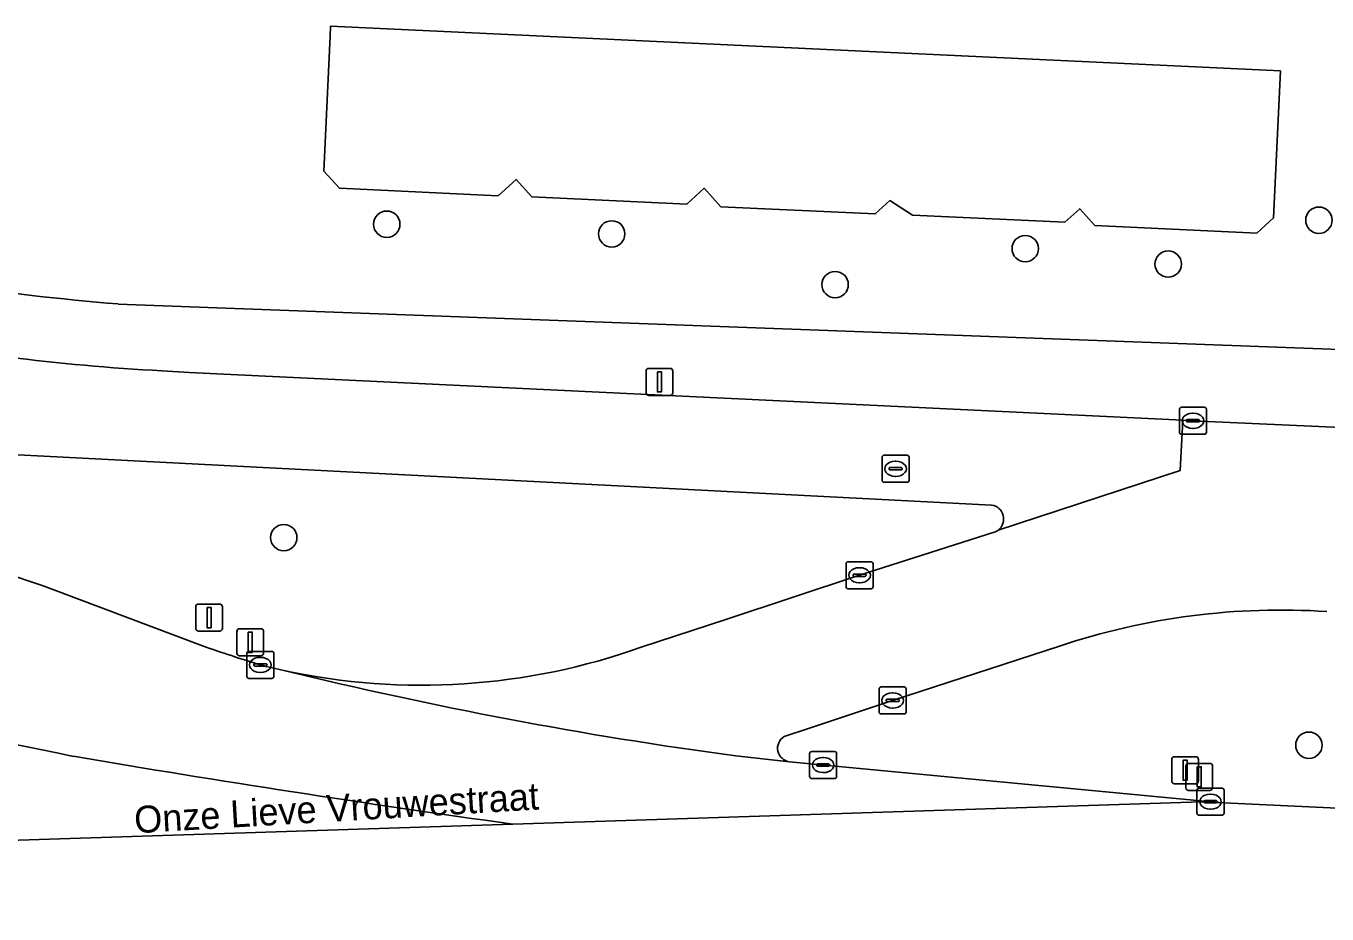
# Model space of a CAD drawing. Extents: x 161248 to 161848, y 384871 to 385383.
# Drawn here: x 161389.28 to 161437.48, y 384880.89 to 384913.79 of the extents above; entities that cross this region are included whole.
import ezdxf

# ---------------------------------------------------------------- set-up
doc = ezdxf.new("R2010")
doc.units = 0
for name, color, linetype in [('IMGEO_Berm_groen', 7, 'Continuous'), ('IMGEO_Boom', 7, 'Continuous'), ('IMGEO_Erf', 7, 'Continuous'), ('IMGEO_Fietspad_gesloten', 7, 'Continuous'), ('IMGEO_Kolk', 7, 'Continuous'), ('IMGEO_Lichtmast', 7, 'Continuous'), ('IMGEO_Openbare_ruimte_label', 7, 'Continuous'), ('IMGEO_Pand', 7, 'Continuous'), ('IMGEO_Rijbaan_lokaal_open', 7, 'Continuous'), ('IMGEO_Rijbaan_regionaal_gesloten', 7, 'Continuous'), ('IMGEO_Rioolput', 7, 'Continuous'), ('IMGEO_Verkeersbordpaal', 7, 'Continuous'), ('IMGEO_Voetpad_open', 7, 'Continuous')]:
    doc.layers.add(name, color=color, linetype=linetype)

msp = doc.modelspace()

# ---------------------------------------------------------------- linework, layer by layer
at = {"layer": 'IMGEO_Berm_groen'}
for points in [[(161425.059, 384896.042), (161385.143, 384898.097)], [(161412.072, 384890.772), (161415.208, 384891.797), (161420.164, 384893.441), (161425.158, 384895.035)], [(161390.211, 384892.939), (161395.816, 384890.82)], [(161427.57, 384890.811), (161421.391, 384888.8), (161418.346, 384887.783), (161417.374, 384887.467)], [(161417.572, 384886.526), (161433.198, 384885.047), (161433.661, 384885.003), (161462.543, 384883.65), (161521.484, 384880.889)], [(161336.645, 384880.9), (161352.375, 384882.439), (161407.315, 384884.216)]]:
    msp.add_lwpolyline(points, dxfattribs=at)
for centre, radius, start, end in [((161424.983, 384895.526), 0.521, 308.0291, 81.6103), ((161360.759, 384809.587), 88.402, 70.53961, 77.01299), ((161424.996, 384895.499), 0.492, 289.245, 308.7976), ((161435.777, 384866.344), 25.807, 86.2042, 108.542), ((161522.417, 385531.517), 658.036, 256.745177, 258.48305), ((161418.628, 384957.021), 70.021, 250.98646, 252.83384), ((161403.947, 384913.55), 24.183, 257.7953, 289.6306), ((161404.161, 384914.436), 25.095, 255.6989, 257.7469), ((161417.636, 384887.031), 0.509, 120.9475, 262.8176), ((161485.028, 385441.523), 562.698, 260.38423, 262.06157)]:
    msp.add_arc(centre, radius, start, end, dxfattribs=at)
at = {"layer": 'IMGEO_Boom'}
for centre in [(161402.645, 384906.447), (161437.186, 384906.596), (161410.979, 384906.088), (161426.304, 384905.543), (161431.601, 384904.972), (161419.258, 384904.209), (161398.828, 384894.835), (161436.816, 384887.142)]:
    msp.add_circle(centre, 0.489, dxfattribs=at)
at = {"layer": 'IMGEO_Erf'}
msp.add_lwpolyline([(161430.768, 384912.367), (161435.762, 384912.131), (161435.505, 384906.68), (161434.889, 384906.119), (161428.885, 384906.402), (161428.321, 384907.022), (161427.768, 384906.519), (161422.131, 384906.785), (161421.289, 384907.325), (161420.743, 384906.828), (161415.03, 384907.098), (161414.408, 384907.782), (161413.761, 384907.193), (161408.021, 384907.464), (161407.435, 384908.109), (161406.767, 384907.501), (161400.891, 384907.778), (161400.31, 384908.417), (161400.545, 384913.412), (161400.563, 384913.792)], close=True, dxfattribs=at)
msp.add_lwpolyline([(161392.69, 384903.491), (161446.603, 384901.485)], dxfattribs=at)
msp.add_arc((161401.795, 385012.165), 109.054, 258.46978, 265.21062, dxfattribs=at)
at = {"layer": 'IMGEO_Fietspad_gesloten'}
for points in [[(161432.148, 384899.181), (161395.318, 384900.953), (161394.326, 384901.014)], [(161425.304, 384895.116), (161432.042, 384897.321), (161432.148, 384899.181)], [(161385.143, 384898.097), (161425.059, 384896.042)]]:
    msp.add_lwpolyline(points, dxfattribs=at)
for centre, radius, start, end in [((161398.556, 384980.656), 79.754, 262.8094, 266.95981), ((161424.983, 384895.526), 0.521, 308.0291, 81.6103)]:
    msp.add_arc(centre, radius, start, end, dxfattribs=at)
at = {"layer": 'IMGEO_Kolk'}
for p, q in [((161432.018, 384898.738), (161432.018, 384899.59)), ((161432.093, 384899.664), (161432.945, 384899.664)), ((161432.506, 384899.444), (161432.531, 384899.444)), ((161433.019, 384899.59), (161433.019, 384898.738)), ((161432.277, 384899.158), (161432.277, 384899.17)), ((161432.715, 384899.121), (161432.317, 384899.121)), ((161432.32, 384899.207), (161432.718, 384899.207)), ((161432.761, 384899.17), (161432.761, 384899.158)), ((161432.945, 384898.664), (161432.093, 384898.664)), ((161432.529, 384898.884), (161432.504, 384898.884)), ((161419.663, 384893.015), (161419.663, 384893.867)), ((161419.738, 384893.941), (161420.59, 384893.941)), ((161420.151, 384893.721), (161420.176, 384893.721)), ((161420.664, 384893.867), (161420.664, 384893.015)), ((161419.922, 384893.435), (161419.922, 384893.447)), ((161420.36, 384893.398), (161419.962, 384893.398)), ((161419.965, 384893.484), (161420.363, 384893.484)), ((161420.174, 384893.161), (161420.149, 384893.161)), ((161420.406, 384893.447), (161420.406, 384893.435)), ((161420.59, 384892.941), (161419.738, 384892.941)), ((161397.461, 384889.693), (161397.461, 384890.545)), ((161397.536, 384890.619), (161398.388, 384890.619)), ((161397.949, 384890.399), (161397.974, 384890.399)), ((161398.462, 384890.545), (161398.462, 384889.693)), ((161397.72, 384890.113), (161397.72, 384890.125)), ((161398.158, 384890.076), (161397.76, 384890.076)), ((161397.763, 384890.162), (161398.161, 384890.162)), ((161397.972, 384889.839), (161397.947, 384889.839)), ((161398.204, 384890.125), (161398.204, 384890.113)), ((161398.388, 384889.619), (161397.536, 384889.619)), ((161420.965, 384889.3), (161421.817, 384889.3)), ((161420.89, 384888.374), (161420.89, 384889.226)), ((161421.149, 384888.794), (161421.149, 384888.806)), ((161421.192, 384888.843), (161421.59, 384888.843)), ((161421.378, 384889.08), (161421.403, 384889.08)), ((161421.633, 384888.806), (161421.633, 384888.794)), ((161421.891, 384889.226), (161421.891, 384888.374)), ((161421.587, 384888.757), (161421.189, 384888.757)), ((161421.401, 384888.52), (161421.376, 384888.52)), ((161421.817, 384888.3), (161420.965, 384888.3)), ((161418.39, 384886.908), (161419.242, 384886.908)), ((161418.315, 384885.982), (161418.315, 384886.834)), ((161418.574, 384886.402), (161418.574, 384886.414)), ((161418.617, 384886.451), (161419.015, 384886.451)), ((161418.803, 384886.688), (161418.828, 384886.688)), ((161419.058, 384886.414), (161419.058, 384886.402)), ((161419.316, 384886.834), (161419.316, 384885.982)), ((161419.242, 384885.908), (161418.39, 384885.908)), ((161419.012, 384886.365), (161418.614, 384886.365)), ((161418.826, 384886.128), (161418.801, 384886.128)), ((161432.668, 384884.624), (161432.668, 384885.476)), ((161432.743, 384885.55), (161433.595, 384885.55)), ((161433.669, 384885.476), (161433.669, 384884.624)), ((161432.927, 384885.044), (161432.927, 384885.056)), ((161433.365, 384885.007), (161432.967, 384885.007)), ((161432.97, 384885.093), (161433.368, 384885.093)), ((161433.156, 384885.33), (161433.181, 384885.33)), ((161433.411, 384885.056), (161433.411, 384885.044)), ((161433.595, 384884.55), (161432.743, 384884.55)), ((161433.179, 384884.77), (161433.154, 384884.77))]:
    msp.add_line(p, q, dxfattribs=at)
for points in [[(161432.018, 384898.738), (161432.018, 384899.59)], [(161432.093, 384899.664), (161432.945, 384899.664)], [(161433.019, 384899.59), (161433.019, 384898.738)], [(161432.945, 384898.664), (161432.093, 384898.664)], [(161419.663, 384893.015), (161419.663, 384893.867)], [(161419.738, 384893.941), (161420.59, 384893.941)], [(161420.664, 384893.867), (161420.664, 384893.015)], [(161420.59, 384892.941), (161419.738, 384892.941)], [(161397.461, 384889.693), (161397.461, 384890.545)], [(161397.536, 384890.619), (161398.388, 384890.619)], [(161398.462, 384890.545), (161398.462, 384889.693)], [(161398.388, 384889.619), (161397.536, 384889.619)], [(161420.965, 384889.3), (161421.817, 384889.3)], [(161420.89, 384888.374), (161420.89, 384889.226)], [(161421.891, 384889.226), (161421.891, 384888.374)], [(161421.817, 384888.3), (161420.965, 384888.3)], [(161418.39, 384886.908), (161419.242, 384886.908)], [(161418.315, 384885.982), (161418.315, 384886.834)], [(161419.316, 384886.834), (161419.316, 384885.982)], [(161419.242, 384885.908), (161418.39, 384885.908)], [(161432.668, 384884.624), (161432.668, 384885.476)], [(161432.743, 384885.55), (161433.595, 384885.55)], [(161433.669, 384885.476), (161433.669, 384884.624)], [(161433.595, 384884.55), (161432.743, 384884.55)]]:
    msp.add_lwpolyline(points, dxfattribs=at)
for centre, radius, start, end in [((161432.095, 384899.588), 0.0765, 91.552, 178.448), ((161432.095, 384899.588), 0.0765, 91.552, 178.448), ((161432.943, 384899.588), 0.0765, 1.552, 88.448), ((161432.943, 384899.588), 0.0765, 1.552, 88.448), ((161432.317, 384899.167), 0.0403, 85.8775, 175.7526), ((161432.314, 384899.157), 0.0366, 178.938, 274.7102), ((161432.718, 384899.164), 0.043, 264.8664, 352.4533), ((161432.722, 384899.169), 0.0386, 1.7309, 96.639), ((161432.095, 384898.74), 0.0765, 181.552, 268.448), ((161432.095, 384898.74), 0.0765, 181.552, 268.448), ((161432.943, 384898.74), 0.0765, 271.552, 358.448), ((161432.943, 384898.74), 0.0765, 271.552, 358.448), ((161419.74, 384893.865), 0.0765, 91.552, 178.448), ((161419.74, 384893.865), 0.0765, 91.552, 178.448), ((161420.588, 384893.865), 0.0765, 1.552, 88.448), ((161420.588, 384893.865), 0.0765, 1.552, 88.448), ((161419.962, 384893.444), 0.0403, 85.8775, 175.7526), ((161419.959, 384893.434), 0.0366, 178.938, 274.7102), ((161420.363, 384893.441), 0.043, 264.8664, 352.4533), ((161420.367, 384893.446), 0.0386, 1.7309, 96.639), ((161419.74, 384893.017), 0.0765, 181.552, 268.448), ((161419.74, 384893.017), 0.0765, 181.552, 268.448), ((161420.588, 384893.017), 0.0765, 271.552, 358.448), ((161420.588, 384893.017), 0.0765, 271.552, 358.448), ((161397.538, 384890.543), 0.0765, 91.552, 178.448), ((161397.538, 384890.543), 0.0765, 91.552, 178.448), ((161398.386, 384890.543), 0.0765, 1.552, 88.448), ((161398.386, 384890.543), 0.0765, 1.552, 88.448), ((161397.76, 384890.122), 0.0403, 85.8775, 175.7526), ((161397.757, 384890.112), 0.0366, 178.938, 274.7102), ((161398.161, 384890.119), 0.043, 264.8664, 352.4533), ((161398.165, 384890.124), 0.0386, 1.7309, 96.639), ((161397.538, 384889.695), 0.0765, 181.552, 268.448), ((161397.538, 384889.695), 0.0765, 181.552, 268.448), ((161398.386, 384889.695), 0.0765, 271.552, 358.448), ((161398.386, 384889.695), 0.0765, 271.552, 358.448), ((161420.967, 384889.224), 0.0765, 91.552, 178.448), ((161420.967, 384889.224), 0.0765, 91.552, 178.448), ((161421.815, 384889.224), 0.0765, 1.552, 88.448), ((161421.815, 384889.224), 0.0765, 1.552, 88.448), ((161421.189, 384888.803), 0.0403, 85.8775, 175.7526), ((161421.186, 384888.793), 0.0366, 178.938, 274.7102), ((161421.59, 384888.8), 0.043, 264.8664, 352.4533), ((161421.594, 384888.805), 0.0386, 1.7309, 96.639), ((161420.967, 384888.376), 0.0765, 181.552, 268.448), ((161420.967, 384888.376), 0.0765, 181.552, 268.448), ((161421.815, 384888.376), 0.0765, 271.552, 358.448), ((161421.815, 384888.376), 0.0765, 271.552, 358.448), ((161418.392, 384886.832), 0.0765, 91.552, 178.448), ((161418.392, 384886.832), 0.0765, 91.552, 178.448), ((161419.24, 384886.832), 0.0765, 1.552, 88.448), ((161419.24, 384886.832), 0.0765, 1.552, 88.448), ((161418.614, 384886.411), 0.0403, 85.8775, 175.7526), ((161418.611, 384886.401), 0.0366, 178.938, 274.7102), ((161419.015, 384886.408), 0.043, 264.8664, 352.4533), ((161419.019, 384886.413), 0.0386, 1.7309, 96.639), ((161418.392, 384885.984), 0.0765, 181.552, 268.448), ((161418.392, 384885.984), 0.0765, 181.552, 268.448), ((161419.24, 384885.984), 0.0765, 271.552, 358.448), ((161419.24, 384885.984), 0.0765, 271.552, 358.448), ((161432.745, 384885.474), 0.0765, 91.552, 178.448), ((161432.745, 384885.474), 0.0765, 91.552, 178.448), ((161433.593, 384885.474), 0.0765, 1.552, 88.448), ((161433.593, 384885.474), 0.0765, 1.552, 88.448), ((161432.967, 384885.053), 0.0403, 85.8775, 175.7526), ((161432.964, 384885.043), 0.0366, 178.938, 274.7102), ((161433.368, 384885.05), 0.043, 264.8664, 352.4533), ((161433.372, 384885.055), 0.0386, 1.7309, 96.639), ((161432.745, 384884.626), 0.0765, 181.552, 268.448), ((161432.745, 384884.626), 0.0765, 181.552, 268.448), ((161433.593, 384884.626), 0.0765, 271.552, 358.448), ((161433.593, 384884.626), 0.0765, 271.552, 358.448)]:
    msp.add_arc(centre, radius, start, end, dxfattribs=at)
for centre, major_axis, ratio, start_param, end_param in [((161432.505, 384899.164), (-0.387, 0.002), 0.722429, 4.712389, 7.853982), ((161432.53, 384899.164), (-0.39, 0.002), 0.717154, 1.570796, 4.712389), ((161420.15, 384893.441), (-0.387, 0.002), 0.722429, 4.712389, 7.853982), ((161420.175, 384893.441), (-0.39, 0.002), 0.717154, 1.570796, 4.712389), ((161397.948, 384890.119), (-0.387, 0.002), 0.722429, 4.712389, 7.853982), ((161397.973, 384890.119), (-0.39, 0.002), 0.717154, 1.570796, 4.712389), ((161421.377, 384888.8), (-0.387, 0.002), 0.722429, 4.712389, 7.853982), ((161421.402, 384888.8), (-0.39, 0.002), 0.717154, 1.570796, 4.712389), ((161418.802, 384886.408), (-0.387, 0.002), 0.722429, 4.712389, 7.853982), ((161418.827, 384886.408), (-0.39, 0.002), 0.717154, 1.570796, 4.712389), ((161433.155, 384885.05), (-0.387, 0.002), 0.722429, 4.712389, 7.853982), ((161433.18, 384885.05), (-0.39, 0.002), 0.717154, 1.570796, 4.712389)]:
    msp.add_ellipse(centre, major_axis=major_axis, ratio=ratio, start_param=start_param, end_param=end_param, dxfattribs=at)
at = {"layer": 'IMGEO_Lichtmast'}
for p, q in [((161412.255, 384900.206), (161412.255, 384901.006)), ((161412.255, 384901.006), (161412.255, 384900.206)), ((161412.355, 384901.106), (161413.145, 384901.106)), ((161413.145, 384901.106), (161412.355, 384901.106)), ((161413.245, 384901.006), (161413.245, 384900.206)), ((161413.245, 384900.206), (161413.245, 384901.006)), ((161413.145, 384900.106), (161412.355, 384900.106)), ((161412.355, 384900.106), (161413.145, 384900.106)), ((161395.565, 384891.472), (161395.565, 384892.272)), ((161395.565, 384892.272), (161395.565, 384891.472)), ((161395.665, 384892.372), (161396.455, 384892.372)), ((161396.455, 384892.372), (161395.665, 384892.372)), ((161396.555, 384892.272), (161396.555, 384891.472)), ((161396.555, 384891.472), (161396.555, 384892.272)), ((161396.455, 384891.372), (161395.665, 384891.372)), ((161395.665, 384891.372), (161396.455, 384891.372)), ((161431.734, 384885.817), (161431.734, 384886.617)), ((161431.734, 384886.617), (161431.734, 384885.817)), ((161431.834, 384886.717), (161432.624, 384886.717)), ((161432.624, 384886.717), (161431.834, 384886.717)), ((161432.724, 384886.617), (161432.724, 384885.817)), ((161432.724, 384885.817), (161432.724, 384886.617)), ((161432.624, 384885.717), (161431.834, 384885.717)), ((161431.834, 384885.717), (161432.624, 384885.717))]:
    msp.add_line(p, q, dxfattribs=at)
for points in [[(161412.675, 384900.981), (161412.825, 384900.981), (161412.825, 384900.231), (161412.675, 384900.231), (161412.675, 384900.981)], [(161395.985, 384892.247), (161396.135, 384892.247), (161396.135, 384891.497), (161395.985, 384891.497), (161395.985, 384892.247)], [(161432.154, 384886.592), (161432.304, 384886.592), (161432.304, 384885.842), (161432.154, 384885.842), (161432.154, 384886.592)]]:
    msp.add_lwpolyline(points, dxfattribs=at)
for centre, start, end in [((161412.355, 384901.006), 90, 180), ((161412.355, 384901.006), 90, 180), ((161413.145, 384901.006), 0, 90), ((161413.145, 384901.006), 360, 90), ((161412.355, 384900.206), 180, 270), ((161412.355, 384900.206), 180, 270), ((161413.145, 384900.206), 270, 0), ((161413.145, 384900.206), 270, 0), ((161395.665, 384892.272), 90, 180), ((161395.665, 384892.272), 90, 180), ((161396.455, 384892.272), 0, 90), ((161396.455, 384892.272), 360, 90), ((161395.665, 384891.472), 180, 270), ((161395.665, 384891.472), 180, 270), ((161396.455, 384891.472), 270, 0), ((161396.455, 384891.472), 270, 0), ((161431.834, 384886.617), 90, 180), ((161431.834, 384886.617), 90, 180), ((161432.624, 384886.617), 0, 90), ((161432.624, 384886.617), 360, 90), ((161431.834, 384885.817), 180, 270), ((161431.834, 384885.817), 180, 270), ((161432.624, 384885.817), 270, 0), ((161432.624, 384885.817), 270, 0)]:
    msp.add_arc(centre, 0.1, start, end, dxfattribs=at)
at = {"layer": 'IMGEO_Pand'}
msp.add_lwpolyline([(161400.31, 384908.417), (161400.891, 384907.778), (161406.767, 384907.501), (161407.435, 384908.109), (161408.021, 384907.464), (161413.761, 384907.193), (161414.408, 384907.782), (161415.03, 384907.098), (161420.743, 384906.828), (161421.289, 384907.325), (161422.131, 384906.785), (161427.768, 384906.519), (161428.321, 384907.022), (161428.885, 384906.402), (161434.889, 384906.119), (161435.505, 384906.68), (161435.762, 384912.131), (161430.768, 384912.367), (161400.563, 384913.792), (161400.545, 384913.412)], close=True, dxfattribs=at)
at = {"layer": 'IMGEO_Rijbaan_lokaal_open'}
for points in [[(161447.197, 384898.503), (161445.976, 384898.555), (161432.519, 384899.164), (161432.148, 384899.181), (161432.042, 384897.321), (161425.304, 384895.116)], [(161425.158, 384895.035), (161420.164, 384893.441), (161415.208, 384891.797), (161412.072, 384890.772)], [(161417.374, 384887.467), (161418.346, 384887.783), (161421.391, 384888.8), (161427.57, 384890.811)], [(161415.575, 384886.745), (161417.572, 384886.526)]]:
    msp.add_lwpolyline(points, dxfattribs=at)
for centre, radius, start, end in [((161424.996, 384895.499), 0.492, 289.245, 308.7976), ((161435.777, 384866.344), 25.807, 86.2042, 108.542), ((161403.947, 384913.55), 24.183, 257.7953, 289.6306), ((161437.172, 385046.676), 161.382, 256.2579, 262.30943), ((161417.636, 384887.031), 0.509, 120.9475, 262.8176)]:
    msp.add_arc(centre, radius, start, end, dxfattribs=at)
at = {"layer": 'IMGEO_Rijbaan_regionaal_gesloten'}
for points in [[(161395.816, 384890.82), (161390.211, 384892.939)], [(161433.661, 384885.003), (161433.198, 384885.047), (161417.572, 384886.526), (161415.575, 384886.745)], [(161407.315, 384884.216), (161432.831, 384885.042), (161433.661, 384885.003)]]:
    msp.add_lwpolyline(points, dxfattribs=at)
for centre, radius, start, end in [((161360.759, 384809.587), 88.402, 70.53961, 77.01299), ((161522.417, 385531.517), 658.036, 256.745177, 258.48305), ((161418.628, 384957.021), 70.021, 250.98646, 252.83384), ((161404.161, 384914.436), 25.095, 255.6989, 257.7469), ((161437.172, 385046.676), 161.382, 256.2579, 262.30943), ((161485.028, 385441.523), 562.698, 260.38423, 262.06157)]:
    msp.add_arc(centre, radius, start, end, dxfattribs=at)
at = {"layer": 'IMGEO_Rioolput'}
for p, q in [((161420.998, 384896.959), (161420.998, 384897.811)), ((161421.073, 384897.885), (161421.925, 384897.885)), ((161421.486, 384897.665), (161421.511, 384897.665)), ((161421.999, 384897.811), (161421.999, 384896.959)), ((161421.257, 384897.379), (161421.257, 384897.391)), ((161421.695, 384897.342), (161421.297, 384897.342)), ((161421.3, 384897.428), (161421.698, 384897.428)), ((161421.509, 384897.105), (161421.484, 384897.105)), ((161421.741, 384897.391), (161421.741, 384897.379)), ((161421.925, 384896.885), (161421.073, 384896.885))]:
    msp.add_line(p, q, dxfattribs=at)
for points in [[(161420.998, 384896.959), (161420.998, 384897.811)], [(161421.073, 384897.885), (161421.925, 384897.885)], [(161421.999, 384897.811), (161421.999, 384896.959)], [(161421.925, 384896.885), (161421.073, 384896.885)]]:
    msp.add_lwpolyline(points, dxfattribs=at)
for centre, radius, start, end in [((161421.075, 384897.809), 0.0765, 91.552, 178.448), ((161421.075, 384897.809), 0.0765, 91.552, 178.448), ((161421.923, 384897.809), 0.0765, 1.552, 88.448), ((161421.923, 384897.809), 0.0765, 1.552, 88.448), ((161421.297, 384897.388), 0.0403, 85.8775, 175.7526), ((161421.294, 384897.378), 0.0366, 178.938, 274.7102), ((161421.698, 384897.385), 0.043, 264.8664, 352.4533), ((161421.702, 384897.39), 0.0386, 1.7309, 96.639), ((161421.075, 384896.961), 0.0765, 181.552, 268.448), ((161421.075, 384896.961), 0.0765, 181.552, 268.448), ((161421.923, 384896.961), 0.0765, 271.552, 358.448), ((161421.923, 384896.961), 0.0765, 271.552, 358.448)]:
    msp.add_arc(centre, radius, start, end, dxfattribs=at)
for centre, major_axis, ratio, start_param, end_param in [((161421.485, 384897.385), (-0.387, 0.002), 0.722429, 4.712389, 7.853982), ((161421.51, 384897.385), (-0.39, 0.002), 0.717154, 1.570796, 4.712389)]:
    msp.add_ellipse(centre, major_axis=major_axis, ratio=ratio, start_param=start_param, end_param=end_param, dxfattribs=at)
at = {"layer": 'IMGEO_Verkeersbordpaal'}
for p, q in [((161397.089, 384890.557), (161397.089, 384891.357)), ((161397.089, 384891.357), (161397.089, 384890.557)), ((161397.189, 384891.457), (161397.979, 384891.457)), ((161397.979, 384891.457), (161397.189, 384891.457)), ((161398.079, 384891.357), (161398.079, 384890.557)), ((161398.079, 384890.557), (161398.079, 384891.357)), ((161397.979, 384890.457), (161397.189, 384890.457)), ((161397.189, 384890.457), (161397.979, 384890.457)), ((161432.356, 384886.47), (161433.146, 384886.47)), ((161433.146, 384886.47), (161432.356, 384886.47)), ((161432.256, 384885.57), (161432.256, 384886.37)), ((161432.256, 384886.37), (161432.256, 384885.57)), ((161433.246, 384886.37), (161433.246, 384885.57)), ((161433.246, 384885.57), (161433.246, 384886.37)), ((161433.146, 384885.47), (161432.356, 384885.47)), ((161432.356, 384885.47), (161433.146, 384885.47))]:
    msp.add_line(p, q, dxfattribs=at)
for points in [[(161397.509, 384891.332), (161397.659, 384891.332), (161397.659, 384890.582), (161397.509, 384890.582), (161397.509, 384891.332)], [(161432.676, 384886.345), (161432.826, 384886.345), (161432.826, 384885.595), (161432.676, 384885.595), (161432.676, 384886.345)]]:
    msp.add_lwpolyline(points, dxfattribs=at)
for centre, start, end in [((161397.189, 384891.357), 90, 180), ((161397.189, 384891.357), 90, 180), ((161397.979, 384891.357), 0, 90), ((161397.979, 384891.357), 360, 90), ((161397.189, 384890.557), 180, 270), ((161397.189, 384890.557), 180, 270), ((161397.979, 384890.557), 270, 0), ((161397.979, 384890.557), 270, 0), ((161432.356, 384886.37), 90, 180), ((161432.356, 384886.37), 90, 180), ((161433.146, 384886.37), 0, 90), ((161433.146, 384886.37), 360, 90), ((161432.356, 384885.57), 180, 270), ((161432.356, 384885.57), 180, 270), ((161433.146, 384885.57), 270, 0), ((161433.146, 384885.57), 270, 0)]:
    msp.add_arc(centre, 0.1, start, end, dxfattribs=at)
at = {"layer": 'IMGEO_Voetpad_open'}
for points in [[(161446.603, 384901.485), (161392.69, 384903.491)], [(161394.326, 384901.014), (161395.318, 384900.953), (161432.148, 384899.181), (161432.519, 384899.164), (161445.976, 384898.555), (161447.197, 384898.503)]]:
    msp.add_lwpolyline(points, dxfattribs=at)
for centre, radius, start, end in [((161401.795, 385012.165), 109.054, 258.46978, 265.21062), ((161398.556, 384980.656), 79.754, 262.8094, 266.95981)]:
    msp.add_arc(centre, radius, start, end, dxfattribs=at)

# ---------------------------------------------------------------- texts
at = {"layer": 'IMGEO_Openbare_ruimte_label'}
msp.add_text('Onze Lieve Vrouwestraat', height=1, rotation=3.3833, dxfattribs=at).set_placement((161393.315, 384883.877))

doc.saveas('drawing.dxf')
